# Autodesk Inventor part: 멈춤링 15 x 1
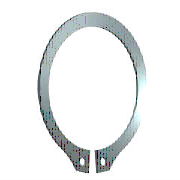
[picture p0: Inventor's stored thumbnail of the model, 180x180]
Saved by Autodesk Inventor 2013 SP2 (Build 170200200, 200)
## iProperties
IsCustomPart: 1
Created: 2012-02
Part Number: 멈춤링 15 x 1
Material: 강철, 연강
Description: 리테이닝 링(C형)
Document SubType Name: Modeling
Standard: KS B 1336
Designer: mduedu
Standards Organization: KS
Language: ko-KR
Size Designation: 15 x 1
Categories: <MemberInstance><Categories><Category DisplayName="샤프트 부품" InternalName="7f7aeb1f-a693-4053-b835-cee3144e0d98" Mnemonic="SHFT"><Category DisplayName="써클립" Inter
Density: 1 g/cm^3
Author: mduedu
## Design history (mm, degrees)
sketch "스케치1"
  geometry: L1 (-6, 0)-(6, 0) reference; L2 (0, 20.189)-(0, -80.536) reference; L3 (-48.09, 0)-(48.09, 0) reference; L4 (-0.425, -14.637)-(-0.425, -18.137); L5 (-0.425, -6.54)-(-0.425, -13.29); L6 (-2.795, 2.1)-(3.672, 2.1); L7 (0.425, -6.54)-(0.425, -13.29); L8 (0.425, -14.637)-(0.425, -18.137); C1 r 0.85 at (-1.7, -16.283); C2 r 0.85 at (1.7, -16.283); A1 r 7.15 centre (0, -7.5) between (0.425, -14.637) and (-0.425, -14.637); A2 r 9.075 centre (0, -6.975) between (4.291, -14.971) and (-4.291, -14.971); A3 r 10.646 centre (0, -7.5) between (-2.023, -17.952) and (-0.425, -18.137); A4 r 1.7 centre (-1.7, -16.283) between (-3.397, -16.376) and (-2.023, -17.952); A5 r 1.7 centre (-5.095, -16.469) between (-3.397, -16.376) and (-4.291, -14.971); A6 r 1.7 centre (5.095, -16.469) between (4.291, -14.971) and (3.397, -16.376); A7 r 1.7 centre (1.7, -16.283) between (2.023, -17.952) and (3.397, -16.376); A8 r 10.646 centre (0, -7.5) between (0.425, -18.137) and (2.023, -17.952)
  constraints: 16 point on circle, 12 end point, 10 centre point, 9 symmetric about line, 5 point on line, 4 tangent, 3 coincident, 2 horizontal, 1 perpendicular, 1 vertical, 5 other
  dimensions: "d0" = 14.3 diameter of A1 (= ND); "d1" = 3.5 distance of L4.end L4.start (= SRB2); "d6" = 0.425 distance between parallel lines of L2 L5 (= 0.25 x SD5); "d7" = 2.1 distance between parallel lines of L6 L3 (= SRB1); "d8" = 0.525 distance of A1.centre A2.centre (= 0.25 x SRB1); "d9" = 1.7 radius of A4 (= SD5); "d10" = 1.7 radius of A5 (= SD5); "d11" = 1.275 distance from line of L4 A4.centre (= 0.75 x SD5); "d12" = 1.7 diameter of C1 (= SD5); "d13" = 1.7 diameter of C2 (= SD5); "d14" = 7.5 distance from line of A1.centre L1 (= 0.5 x WD)
extrude "본체" new body sketch "스케치1" distance "d2" = 1 (= SD); taper "d3" = 0 deg
workaxis "Work Axis1"
workplane "Work Plane1"
body "Solid1"
other parameters: "WD" = 15 (= WDMIN) [user parameter; used in 1 equation term], "SD" = 1 [user parameter; used in 1 equation term], "SRB1" = 2.1 [user parameter; used in 2 equation terms], "ND" = 14.3 [user parameter; used in 1 equation term], "SRB2" = 3.5 [user parameter; used in 1 equation term], "SD5" = 1.7 [user parameter; used in 6 equation terms], "d15" = 0, "d16" = 0, "d17" = 0, "d41" = 0, "d42" = 0, "WDMIN" = 15 [user parameter; used in 1 equation term], "SD3" = 13.8 [user parameter], "WDMAX" = 16 [user parameter]
